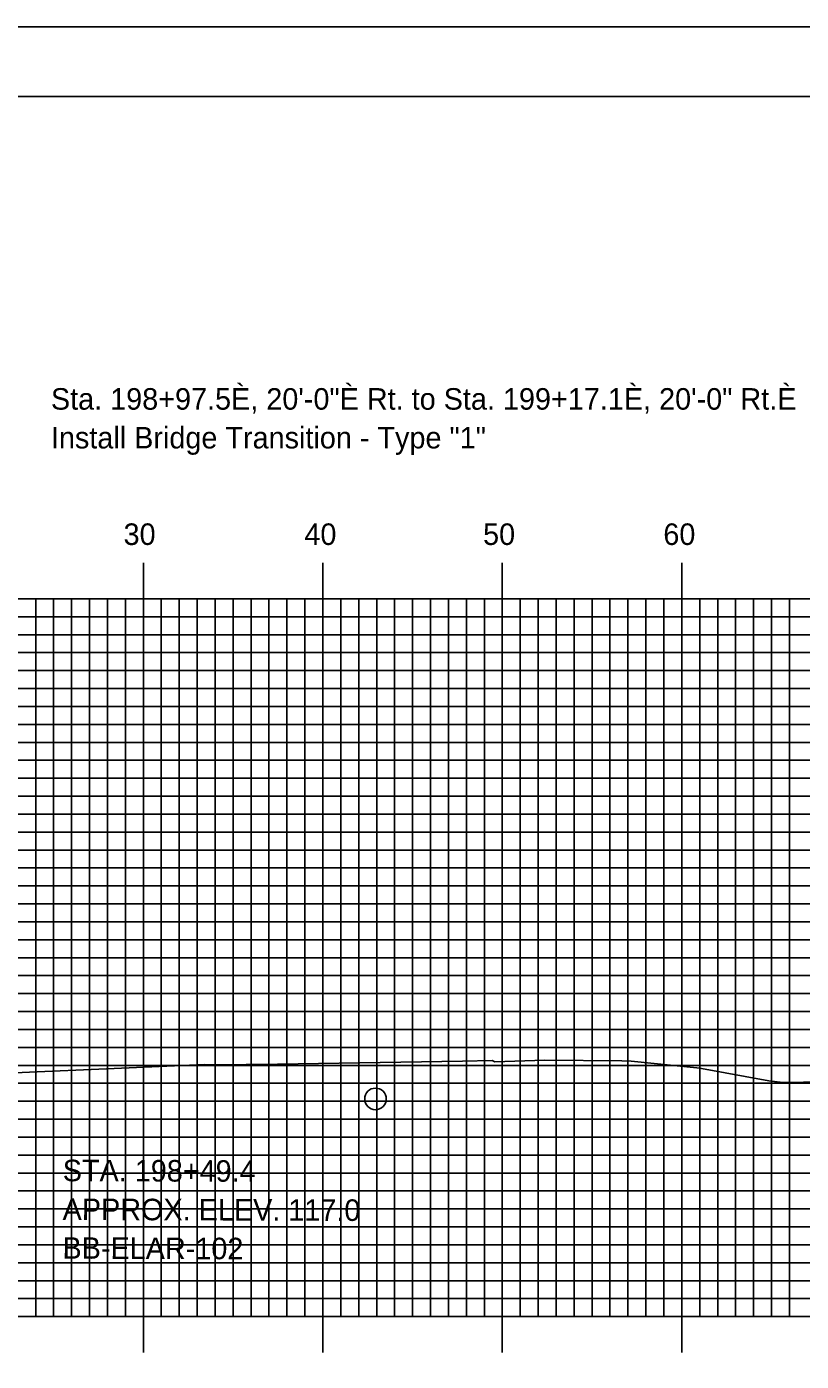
# Model space of a CAD drawing. Extents: x 1790124 to 1790467, y 442591 to 442811.
# Drawn here: x 1790313.2 to 1790356.4, y 442736.2 to 442810.5 of the extents above; entities that cross this region are included whole.
import ezdxf

# ---------------------------------------------------------------- set-up
doc = ezdxf.new("R2010")
doc.units = 0
for name, color, linetype in [('ANNOTATION', 7, 'Continuous'), ('BORDER', 7, 'Continuous'), ('BORING - REFUSAL', 7, 'Continuous'), ('H_V ANNOTATION', 7, 'Continuous'), ('MAJOR', 7, 'Continuous'), ('MINOR', 7, 'Continuous'), ('PLOT BOUNDARY', 7, 'Continuous'), ('S_Drainage_Invert', 7, 'Continuous'), ('S_Roadway_Centerline', 7, 'Continuous')]:
    doc.layers.add(name, color=color, linetype=linetype)

msp = doc.modelspace()

# ---------------------------------------------------------------- linework, layer by layer
at = {"layer": 'BORDER'}
msp.add_lwpolyline([(1790140.096, 442596.665), (1790460.096, 442596.665), (1790460.096, 442806.665), (1790140.096, 442806.665)], close=True, dxfattribs=at)
at = {"layer": 'MAJOR'}
for p, q in [((1790319.696, 442780.669), (1790319.696, 442778.665)), ((1790329.696, 442780.669), (1790329.696, 442778.665)), ((1790339.696, 442780.669), (1790339.696, 442778.665)), ((1790349.696, 442780.669), (1790349.696, 442778.665)), ((1790149.696, 442778.665), (1790429.696, 442778.665)), ((1790149.696, 442778.665), (1790429.696, 442778.665)), ((1790319.696, 442738.665), (1790319.696, 442778.665)), ((1790329.696, 442738.665), (1790329.696, 442778.665)), ((1790339.696, 442738.665), (1790339.696, 442778.665)), ((1790349.696, 442738.665), (1790349.696, 442778.665)), ((1790149.696, 442773.665), (1790429.696, 442773.665)), ((1790149.696, 442768.665), (1790429.696, 442768.665)), ((1790149.696, 442763.665), (1790429.696, 442763.665)), ((1790149.696, 442758.665), (1790429.696, 442758.665)), ((1790149.696, 442753.665), (1790429.696, 442753.665)), ((1790149.696, 442748.665), (1790429.696, 442748.665)), ((1790149.696, 442743.665), (1790429.696, 442743.665)), ((1790149.696, 442738.665), (1790429.696, 442738.665)), ((1790149.696, 442738.665), (1790429.696, 442738.665)), ((1790319.696, 442736.661), (1790319.696, 442738.665)), ((1790329.696, 442736.661), (1790329.696, 442738.665)), ((1790339.696, 442736.661), (1790339.696, 442738.665)), ((1790349.696, 442736.661), (1790349.696, 442738.665))]:
    msp.add_line(p, q, dxfattribs=at)
at = {"layer": 'MINOR'}
for p, q in [((1790313.696, 442738.665), (1790313.696, 442778.665)), ((1790314.696, 442738.665), (1790314.696, 442778.665)), ((1790315.696, 442738.665), (1790315.696, 442778.665)), ((1790316.696, 442738.665), (1790316.696, 442778.665)), ((1790317.696, 442738.665), (1790317.696, 442778.665)), ((1790318.696, 442738.665), (1790318.696, 442778.665)), ((1790320.696, 442738.665), (1790320.696, 442778.665)), ((1790321.696, 442738.665), (1790321.696, 442778.665)), ((1790322.696, 442738.665), (1790322.696, 442778.665)), ((1790323.696, 442738.665), (1790323.696, 442778.665)), ((1790324.696, 442738.665), (1790324.696, 442778.665)), ((1790325.696, 442738.665), (1790325.696, 442778.665)), ((1790326.696, 442738.665), (1790326.696, 442778.665)), ((1790327.696, 442738.665), (1790327.696, 442778.665)), ((1790328.696, 442738.665), (1790328.696, 442778.665)), ((1790330.696, 442738.665), (1790330.696, 442778.665)), ((1790331.696, 442738.665), (1790331.696, 442778.665)), ((1790332.696, 442738.665), (1790332.696, 442778.665)), ((1790333.696, 442738.665), (1790333.696, 442778.665)), ((1790334.696, 442738.665), (1790334.696, 442778.665)), ((1790335.696, 442738.665), (1790335.696, 442778.665)), ((1790336.696, 442738.665), (1790336.696, 442778.665)), ((1790337.696, 442738.665), (1790337.696, 442778.665)), ((1790338.696, 442738.665), (1790338.696, 442778.665)), ((1790340.696, 442738.665), (1790340.696, 442778.665)), ((1790341.696, 442738.665), (1790341.696, 442778.665)), ((1790342.696, 442738.665), (1790342.696, 442778.665)), ((1790343.696, 442738.665), (1790343.696, 442778.665)), ((1790344.696, 442738.665), (1790344.696, 442778.665)), ((1790345.696, 442738.665), (1790345.696, 442778.665)), ((1790346.696, 442738.665), (1790346.696, 442778.665)), ((1790347.696, 442738.665), (1790347.696, 442778.665)), ((1790348.696, 442738.665), (1790348.696, 442778.665)), ((1790350.696, 442738.665), (1790350.696, 442778.665)), ((1790351.696, 442738.665), (1790351.696, 442778.665)), ((1790352.696, 442738.665), (1790352.696, 442778.665)), ((1790353.696, 442738.665), (1790353.696, 442778.665)), ((1790354.696, 442738.665), (1790354.696, 442778.665)), ((1790355.696, 442738.665), (1790355.696, 442778.665)), ((1790149.696, 442777.665), (1790429.696, 442777.665)), ((1790149.696, 442776.665), (1790429.696, 442776.665)), ((1790149.696, 442775.665), (1790429.696, 442775.665)), ((1790149.696, 442774.665), (1790429.696, 442774.665)), ((1790149.696, 442772.665), (1790429.696, 442772.665)), ((1790149.696, 442771.665), (1790429.696, 442771.665)), ((1790149.696, 442770.665), (1790429.696, 442770.665)), ((1790149.696, 442769.665), (1790429.696, 442769.665)), ((1790149.696, 442767.665), (1790429.696, 442767.665)), ((1790149.696, 442766.665), (1790429.696, 442766.665)), ((1790149.696, 442765.665), (1790429.696, 442765.665)), ((1790149.696, 442764.665), (1790429.696, 442764.665)), ((1790149.696, 442762.665), (1790429.696, 442762.665)), ((1790149.696, 442761.665), (1790429.696, 442761.665)), ((1790149.696, 442760.665), (1790429.696, 442760.665)), ((1790149.696, 442759.665), (1790429.696, 442759.665)), ((1790149.696, 442757.665), (1790429.696, 442757.665)), ((1790149.696, 442756.665), (1790429.696, 442756.665)), ((1790149.696, 442755.665), (1790429.696, 442755.665)), ((1790149.696, 442754.665), (1790429.696, 442754.665)), ((1790149.696, 442752.665), (1790429.696, 442752.665)), ((1790149.696, 442751.665), (1790429.696, 442751.665)), ((1790149.696, 442750.665), (1790429.696, 442750.665)), ((1790149.696, 442749.665), (1790429.696, 442749.665)), ((1790149.696, 442747.665), (1790429.696, 442747.665)), ((1790149.696, 442746.665), (1790429.696, 442746.665)), ((1790149.696, 442745.665), (1790429.696, 442745.665)), ((1790149.696, 442744.665), (1790429.696, 442744.665)), ((1790149.696, 442742.665), (1790429.696, 442742.665)), ((1790149.696, 442741.665), (1790429.696, 442741.665)), ((1790149.696, 442740.665), (1790429.696, 442740.665)), ((1790149.696, 442739.665), (1790429.696, 442739.665))]:
    msp.add_line(p, q, dxfattribs=at)
at = {"layer": 'PLOT BOUNDARY'}
msp.add_lwpolyline([(1790123.909, 442590.547), (1790463.909, 442590.547), (1790463.909, 442810.547), (1790123.909, 442810.547)], close=True, dxfattribs=at)
at = {"layer": 'S_Drainage_Invert'}
msp.add_circle((1790332.629, 442750.795), 0.6, dxfattribs=at)
at = {"layer": 'S_Roadway_Centerline'}
msp.add_lwpolyline([(1790309.21, 442752.099), (1790313.351, 442752.288), (1790317.65, 442752.467), (1790323.094, 442752.72), (1790323.666, 442752.695), (1790327.167, 442752.722), (1790337.48, 442752.899), (1790339.133, 442752.937), (1790339.272, 442752.86), (1790342.071, 442752.953), (1790346.362, 442752.919), (1790346.879, 442752.902), (1790350.529, 442752.528), (1790350.665, 442752.513), (1790350.796, 442752.487), (1790354.546, 442751.805), (1790355.325, 442751.717), (1790355.84, 442751.702), (1790357.731, 442751.773)], dxfattribs=at)

# ---------------------------------------------------------------- texts
at = {"layer": 'ANNOTATION'}
for s, p in [('Sta. 198+97.5È, 20\'-0"È Rt. to Sta. 199+17.1È, 20\'-0" Rt.È', (1790314.546, 442789.204)), ('Install Bridge Transition - Type "1"', (1790314.546, 442787.044))]:
    msp.add_text(s, height=1.2, dxfattribs=at).set_placement(p)
at = {"layer": 'BORING - REFUSAL'}
for s, p in [('STA. 198+49.4', (1790315.202, 442746.208)), ('APPROX. ELEV. 117.0', (1790315.195, 442744.048)), ('BB-ELAR-102', (1790315.188, 442741.888))]:
    msp.add_text(s, height=1.2, rotation=359.81416, dxfattribs=at).set_placement(p)
at = {"layer": 'H_V ANNOTATION'}
for s, p in [('30', (1790318.593, 442781.665)), ('40', (1790328.668, 442781.665)), ('50', (1790338.625, 442781.665)), ('60', (1790348.668, 442781.665))]:
    msp.add_text(s, height=1.2, dxfattribs=at).set_placement(p)
at = {"layer": 'S_Roadway_Centerline'}
for s, p in [('C', (1790323.089, 442752.72)), ('C', (1790323.089, 442752.72)), ('L', (1790323.094, 442752.713)), ('L', (1790323.094, 442752.713))]:
    msp.add_text(s, height=0.0146, dxfattribs=at).set_placement(p)

doc.saveas('drawing.dxf')
